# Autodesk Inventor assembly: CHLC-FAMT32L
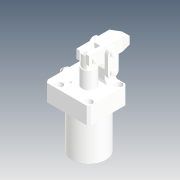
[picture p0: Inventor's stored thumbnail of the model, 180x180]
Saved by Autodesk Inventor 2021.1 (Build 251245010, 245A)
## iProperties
Created: 2019-04
Part Number: CHLC-FAMT32L
Description: STEP AP214
Document SubType Name: Assembly
Designer: user
Title: CHLC-FAMT32L.STEP
Revision Number: ÈÎºÎ
Sending System: SolidWorks 2016
Preprocessor: SwSTEP 2.0
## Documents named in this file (11)
- D:\Vault_2016\Projekty\Clamptek\Hydraulic\CHLC\CHLC-32\Inventor\CHLC-FAMT32L\CHLC-FAMT32L.iam
- D:\Vault_2016\Projekty\Clamptek\Hydraulic\CHLC\CHLC-32\Inventor\CHLC-FAMT32L\benti.ipt
- D:\Vault_2016\Projekty\Clamptek\Hydraulic\CHLC\CHLC-32\Inventor\CHLC-FAMT32L\CHLC-32-02_1.ipt
- D:\Vault_2016\Projekty\Clamptek\Hydraulic\CHLC\CHLC-32\Inventor\CHLC-FAMT32L\CHLC-32-03_1.ipt
- D:\Vault_2016\Projekty\Clamptek\Hydraulic\CHLC\CHLC-32\Inventor\CHLC-FAMT32L\CHLC-32-04_1_1.ipt
- D:\Vault_2016\Projekty\Clamptek\Hydraulic\CHLC\CHLC-32\Inventor\CHLC-FAMT32L\CHLC-32-08_1.ipt
- D:\Vault_2016\Projekty\Clamptek\Hydraulic\CHLC\CHLC-32\Inventor\CHLC-FAMT32L\chlc-famT32BT-HANJIE.ipt
- D:\Vault_2016\Projekty\Clamptek\Hydraulic\CHLC\CHLC-32\Inventor\CHLC-FAMT32L\CZL10µ÷ËÙ·§_1.ipt
- D:\Vault_2016\Projekty\Clamptek\Hydraulic\CHLC\CHLC-32\Inventor\CHLC-FAMT32L\socket set screw flat point_iso_ISO 4026 - M5 x 6-S.ipt
- D:\Vault_2016\Projekty\Clamptek\Hydraulic\CHLC\CHLC-32\Inventor\CHLC-FAMT32L\LHC01D-32-01_1.ipt
- D:\Vault_2016\Projekty\Clamptek\Hydraulic\CHLC\CHLC-32\Inventor\CHLC-FAMT32L\Ñ¹±Û.ipt
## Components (17 placed, 17 different names)
1. benti_1
2. CHLC-32-02_1_2
3. CHLC-32-03_1_3
4. CHLC-32-04_1_1_4
5. CHLC-32-08_1_5
6. chlc-famT32BT-HANJIE_6
7. CZL10µ÷ËÙ·§_1_7
8. socket set screw flat point_iso_ISO 4026 - M5 x 6-S_8
9. CHLC-32-03_1_9
10. LHC01D-32-01_1_10
11. LHC01D-32-01_1_11
12. LHC01D-32-01_1_12
13. LHC01D-32-01_1_13
14. LHC01D-32-01_1_14
15. LHC01D-32-01_1_15
16. CHLC-32-04_1_1_16
17. Ñ¹±Û_17
